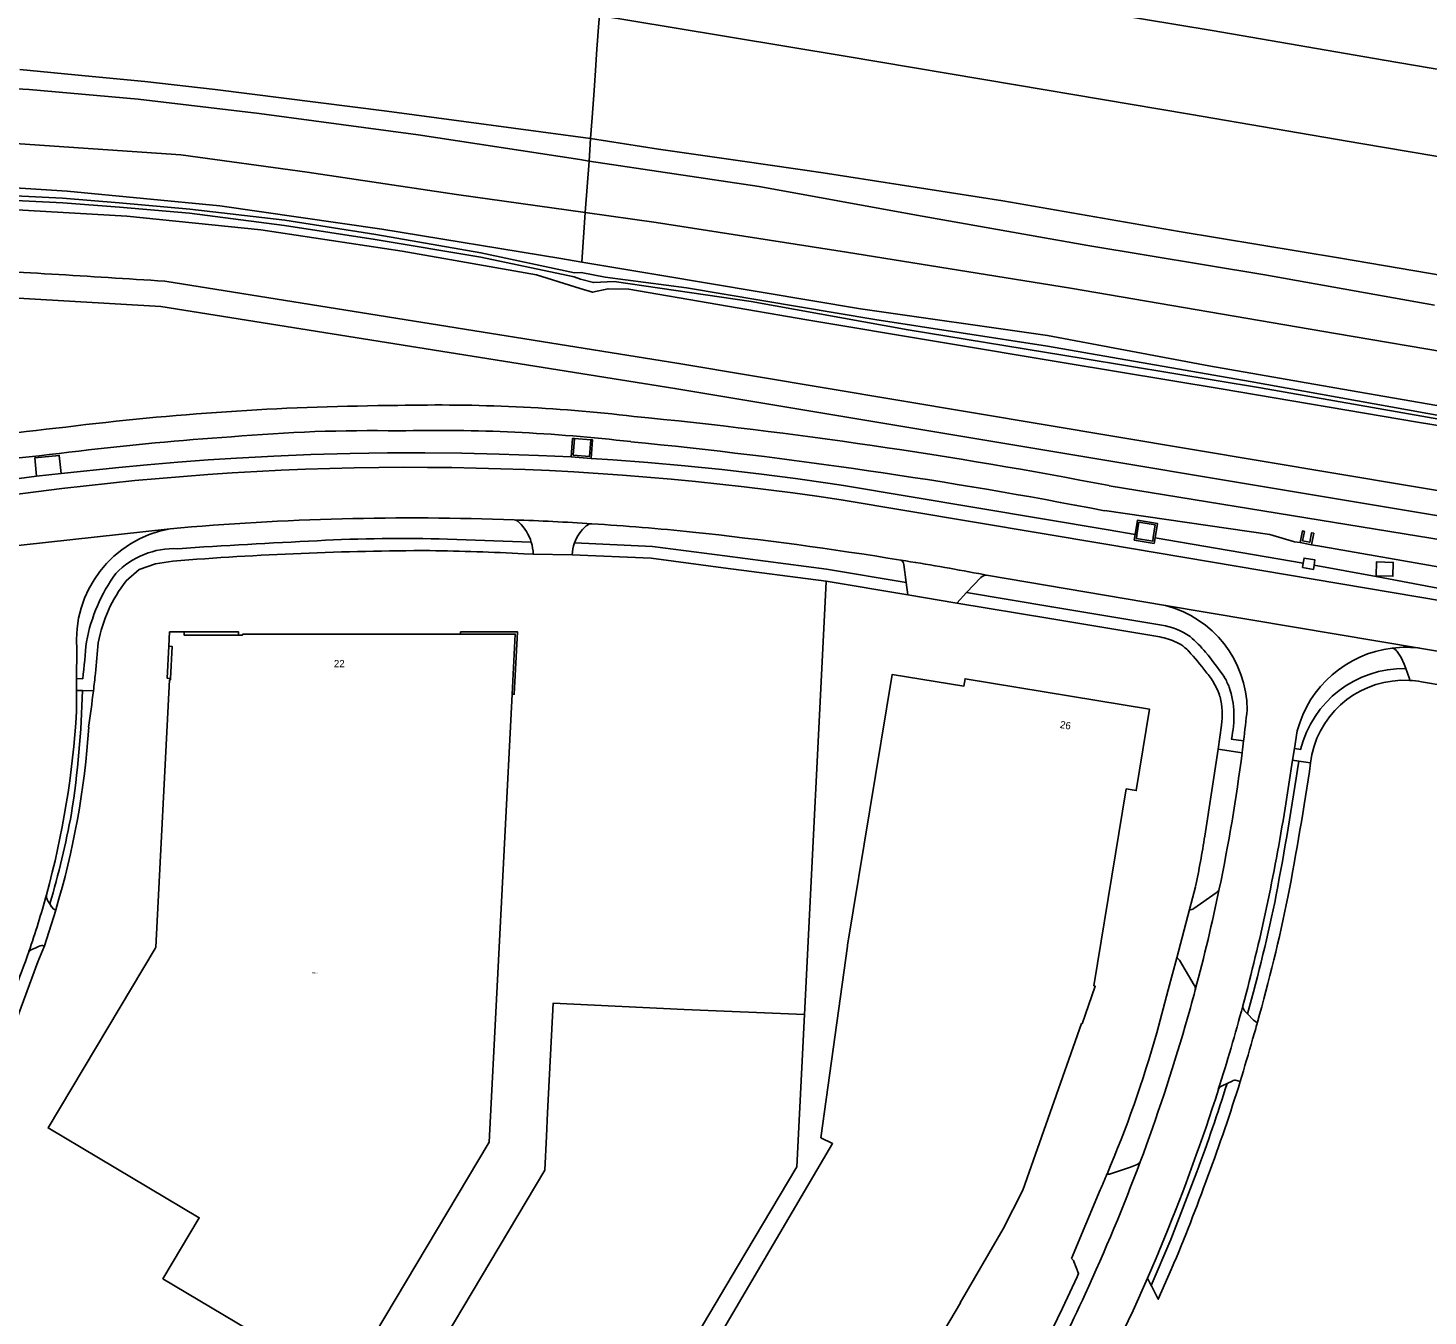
# Model space of a CAD drawing. Extents: x 124000 to 129000, y 395500 to 397503.
# Drawn here: x 125266.3 to 125459, y 395655.6 to 395832.9 of the extents above; entities that cross this region are included whole.
import ezdxf

# ---------------------------------------------------------------- set-up
doc = ezdxf.new("R2010")
doc.units = 0
for name, color, linetype in [('gg-anno-huisnummerreeks BGT', 7, 'Continuous'), ('gg-bbg-luifel en loopbrug', 7, 'Continuous'), ('gg-knt-BGT kruinlijn', 7, 'Continuous'), ('gx-grn-maaiveld', 7, 'Continuous'), ('kenmerkpunt-x pandkandidaat', 7, 'Continuous')]:
    doc.layers.add(name, color=color, linetype=linetype)

msp = doc.modelspace()

# ---------------------------------------------------------------- linework, layer by layer
at = {"layer": 'gg-bbg-luifel en loopbrug'}
for points in [[(125287.82, 395749.78), (125287.82, 395749.35), (125295.32, 395749.35)], [(125287.82, 395749.78), (125295.32, 395749.78), (125295.32, 395749.35)], [(125325.89, 395749.48), (125325.88, 395749.79), (125333.71, 395749.8), (125333.27, 395741.21), (125332.97, 395741.21)], [(125285.95, 395743.39), (125285.51, 395743.41), (125285.74, 395747.81)], [(125285.95, 395743.39), (125286.17, 395747.79), (125285.74, 395747.81)], [(125325.89, 395749.48), (125333.4, 395749.49), (125332.97, 395741.21)]]:
    msp.add_lwpolyline(points, dxfattribs=at)
at = {"layer": 'gg-knt-BGT kruinlijn'}
for p, q in [((125249, 395825.44), (125266.49, 395824.45)), ((125266.49, 395824.45), (125281.51, 395823.15)), ((125281.51, 395823.15), (125298.16, 395821.18)), ((125298.16, 395821.18), (125320.05, 395818.24)), ((125320.05, 395818.24), (125342.31, 395814.81)), ((125342.31, 395814.81), (125343.56, 395814.62)), ((125343.56, 395814.62), (125366.96, 395811.12)), ((125366.96, 395811.12), (125388.64, 395807.15)), ((125388.64, 395807.15), (125412.21, 395803.01)), ((125412.21, 395803.01), (125436.6, 395798.97)), ((125436.6, 395798.97), (125459.92, 395794.76))]:
    msp.add_line(p, q, dxfattribs=at)
at = {"layer": 'gx-grn-maaiveld'}
for p, q in [((125343.56, 395814.62), (125343.78, 395817.71)), ((125343.56, 395814.62), (125343.05, 395807.51)), ((125343.05, 395807.51), (125342.57, 395800.71)), ((125343.81, 395776.23), (125341.54, 395776.41)), ((125341.09, 395773.91), (125343.86, 395773.68)), ((125267.51, 395771.25), (125270.88, 395771.59)), ((125271, 395769.51), (125261.18, 395768.27)), ((125415.17, 395769.92), (125490.09, 395757.69)), ((125249.64, 395759.98), (125285.9, 395764)), ((125335.61, 395762.16), (125324.06, 395762.55)), ((125421.48, 395762.74), (125441.88, 395759.24)), ((125441.44, 395762.09), (125443.02, 395761.78)), ((125334.58, 395760.55), (125335.88, 395760.5)), ((125341.23, 395760.41), (125335.88, 395760.5)), ((125387.22, 395756.57), (125386.9, 395759.09)), ((125398.26, 395757.62), (125397.2, 395757.81)), ((125398.26, 395757.62), (125422.91, 395753.4)), ((125387.44, 395754.87), (125376.2, 395756.78)), ((125387.44, 395754.87), (125387.22, 395756.57)), ((125397.5, 395757.29), (125395.53, 395755.19)), ((125394.18, 395753.75), (125387.44, 395754.87)), ((125394.18, 395753.75), (125395.53, 395755.19)), ((125458.17, 395747.52), (125422.91, 395753.4)), ((125273.05, 395747.27), (125273.03, 395743.36)), ((125466.36, 395746.12), (125458.17, 395747.52)), ((125273.03, 395743.36), (125273.02, 395741.72)), ((125273.03, 395743.36), (125273.88, 395743.34)), ((125458.13, 395742.91), (125461.4, 395742.35)), ((125273.02, 395741.72), (125273.01, 395738.82)), ((125273.82, 395741.71), (125273.02, 395741.72)), ((125275.34, 395741.69), (125273.82, 395741.71)), ((125430.18, 395733.63), (125430.62, 395736.95)), ((125441.03, 395736.16), (125440.65, 395733.73)), ((125433.66, 395734.78), (125431.97, 395735.04)), ((125430.18, 395733.63), (125428.31, 395721.68)), ((125433.46, 395733.16), (125430.18, 395733.63)), ((125440.65, 395733.73), (125440.4, 395732.11)), ((125440.65, 395733.73), (125441.52, 395733.59)), ((125440.4, 395732.11), (125439.37, 395725.51)), ((125441.26, 395731.98), (125440.4, 395732.11)), ((125441.26, 395731.98), (125442.89, 395731.74)), ((125427.04, 395714.71), (125426.2, 395711.55)), ((125429.89, 395713.88), (125426.82, 395711.69)), ((125270.15, 395711.49), (125268.6, 395706.57)), ((125269.34, 395712.34), (125269.06, 395712.77)), ((125269.59, 395711.94), (125269.34, 395712.34)), ((125426.2, 395711.55), (125424.45, 395704.91)), ((125424.83, 395704.57), (125426.88, 395701.16)), ((125409.99, 395663.51), (125413.94, 395672.96)), ((125420.43, 395660.79), (125420.95, 395659.78))]:
    msp.add_line(p, q, dxfattribs=at)
for points in [[(125345.82, 395846.55), (125359.02, 395844.27), (125382.53, 395840.39), (125405.97, 395836.45), (125429.34, 395832.58), (125453, 395828.49), (125476.47, 395824.51), (125500.09, 395820.42), (125523.87, 395816.31), (125547.16, 395812.24), (125570.39, 395808.12), (125593.59, 395803.85), (125601.6, 395802.35)], [(125344.98, 395834.66), (125344.9, 395833.63), (125344.65, 395830), (125344.39, 395826.38), (125344.25, 395824.33), (125343.98, 395820.61), (125343.78, 395817.71)], [(125344.98, 395834.66), (125354.72, 395833.06), (125378.81, 395829.06), (125402.27, 395825.11), (125426.2, 395821.07), (125449.79, 395817.05), (125473.42, 395813.02), (125497.28, 395808.92), (125520.58, 395804.95), (125544.59, 395800.78), (125567.99, 395796.56), (125591.71, 395792.24), (125614.95, 395787.93), (125638.82, 395783.33), (125662.54, 395778.66), (125685.78, 395773.83), (125713.39, 395767.84)], [(125265.21, 395827.21), (125274.22, 395826.33), (125282.42, 395825.55), (125292.12, 395824.46), (125315.71, 395821.5), (125343.78, 395817.71)], [(125343.05, 395807.51), (125325.34, 395809.99), (125304.78, 395813.08), (125287.39, 395815.49), (125265.27, 395816.98), (125249.19, 395817.58), (125228.59, 395817.85), (125207.15, 395818.11), (125183.87, 395817.63), (125158.24, 395817.47), (125133.43, 395817.52), (125099.73, 395817.55), (125068.88, 395817.77), (125053.79, 395818.14), (125033.24, 395818.34), (125017.43, 395818.54), (125006.18, 395819.09), (124994.47, 395819.98), (124980.21, 395821.12), (124962.85, 395822.35)], [(124962.28, 395818.57), (124972.22, 395817.56), (124999.7, 395815.15), (125016.69, 395813.88), (125039.53, 395813.01), (125062.11, 395812.56), (125082.26, 395812.22), (125109.45, 395811.99), (125134.05, 395811.74), (125159.11, 395811.6), (125182.8, 395811.62), (125228, 395812.21), (125250.9, 395811.79), (125271.73, 395810.48), (125292.72, 395808.46), (125315.02, 395805.25), (125339.66, 395801.2), (125342.57, 395800.71)], [(125713.06, 395753.85), (125707.17, 395754.82), (125682.9, 395759.05), (125660.68, 395763.07), (125637.62, 395767.22), (125613, 395771.82), (125588.75, 395776.22), (125566.11, 395780.39), (125542.27, 395784.45), (125518.89, 395788.81), (125495.11, 395792.93), (125471.25, 395797.12), (125447, 395801.24), (125424.8, 395804.9), (125400.53, 395809.12), (125375.8, 395812.98), (125364.69, 395814.58), (125353.12, 395816.27), (125343.78, 395817.71)], [(125345.77, 395798.65), (125342.47, 395799.26), (125341.57, 395799.24), (125328.68, 395802), (125314.21, 395804.49), (125301.68, 395806.48), (125288.6, 395807.97), (125278.88, 395808.86), (125271.1, 395809.51), (125260.79, 395810.03)], [(125260.88, 395809.38), (125271.14, 395808.87), (125278.95, 395808.27), (125288.56, 395807.44), (125301.62, 395805.75), (125314.11, 395803.82), (125328.65, 395801.39), (125341.51, 395798.69), (125342.4, 395798.35), (125344.17, 395797.88), (125347.02, 395798.02), (125365.9, 395795.27), (125387.48, 395791.36), (125411.57, 395787.44), (125435.97, 395783.39), (125462.37, 395778.77), (125490.69, 395774.17), (125518.69, 395769.47), (125541.43, 395766.47), (125564.06, 395762.87), (125584.4, 395759.25)], [(125502.73, 395771.37), (125484.7, 395774.24), (125457.62, 395778.68), (125430.56, 395783.27), (125409.25, 395786.8), (125373.53, 395792.76), (125349.02, 395796.99), (125346.19, 395797.04), (125344.06, 395796.55), (125342.32, 395797.09), (125336.35, 395798.96), (125317.83, 395802.21), (125298.38, 395805.14), (125279.92, 395807.03), (125261.58, 395808.1)], [(125712.87, 395745.87), (125701.58, 395748.17), (125675.43, 395752.9), (125649.11, 395757.15), (125626.09, 395761.17), (125601.29, 395765.34), (125574.24, 395770.23), (125543.08, 395774.92), (125512.53, 395780.27), (125480.9, 395784.98), (125446.33, 395790.87), (125409.82, 395797.11), (125379, 395802.07), (125352.78, 395806.15), (125343.05, 395807.51)], [(125342.57, 395800.71), (125353.3, 395798.89), (125380.93, 395794.29)], [(125493.38, 395763.53), (125486.66, 395764.85), (125355.93, 395786.76), (125285.18, 395798.07)], [(125598.31, 395757.26), (125575.93, 395761.16), (125553.6, 395764.89), (125529.52, 395768.4), (125508.41, 395771.71), (125485.63, 395775.64), (125461.32, 395779.46), (125434.56, 395784.27), (125406.65, 395789.13), (125382.92, 395792.78), (125356.96, 395797.14), (125345.77, 395798.65)], [(125491.34, 395760.61), (125355.38, 395783.3), (125284.63, 395794.61), (125253.93, 395796.4)], [(125428.89, 395786.41), (125406.65, 395790.59), (125380.93, 395794.29)], [(125486.61, 395776.68), (125467.43, 395779.73), (125448.34, 395783.04), (125428.89, 395786.41)], [(125341.54, 395776.41), (125341.29, 395776.43), (125341.09, 395773.91)], [(125343.81, 395776.23), (125343.63, 395773.95), (125341.36, 395774.14), (125341.54, 395776.41)], [(125343.86, 395773.68), (125344.06, 395776.21), (125343.81, 395776.23)], [(125267.51, 395771.25), (125267.26, 395773.74), (125270.64, 395774.08), (125270.88, 395771.59)], [(125270.88, 395771.59), (125278.84, 395772.4), (125282.74, 395772.78), (125286.94, 395773.14), (125291.14, 395773.46), (125295.05, 395773.72), (125300.17, 395774), (125305.28, 395774.21), (125310.7, 395774.36), (125315.82, 395774.43), (125320.94, 395774.44), (125326.07, 395774.38), (125331.19, 395774.26), (125336.6, 395774.06), (125341.09, 395773.91)], [(125418.74, 395763.21), (125415.01, 395763.85), (125378.57, 395769.95), (125376.76, 395770.22), (125372, 395770.89), (125366.92, 395771.54), (125361.83, 395772.13), (125356.74, 395772.65), (125351.64, 395773.1), (125346.83, 395773.47), (125343.86, 395773.68)], [(125267.51, 395771.25), (125255.52, 395769.63), (125248.38, 395768.88), (125241.23, 395768.21), (125233.21, 395767.58), (125225.19, 395767.05), (125217.44, 395766.64), (125209.41, 395766.33), (125201.37, 395766.12), (125193.33, 395766.03), (125185.29, 395766.05), (125177.25, 395766.17), (125169.5, 395766.4), (125161.75, 395766.72), (125158.03, 395766.92), (125143.8, 395767.8)], [(125479.12, 395751.01), (125414.68, 395761.88), (125378.26, 395767.97)], [(125441.44, 395762.09), (125440.67, 395762.2), (125437.28, 395763.19), (125414.5, 395766.48)], [(125421.48, 395762.74), (125421.8, 395764.73), (125419.05, 395765.17), (125418.74, 395763.21)], [(125418.74, 395763.21), (125418.61, 395762.42), (125421.35, 395761.98), (125421.48, 395762.74)], [(125421.23, 395762.78), (125421.15, 395762.27), (125418.9, 395762.63), (125418.98, 395763.17), (125419.26, 395764.88), (125421.51, 395764.52), (125421.23, 395762.78)], [(125443.02, 395761.78), (125443.33, 395763.37), (125443.03, 395763.43), (125442.78, 395762.13), (125441.79, 395762.33), (125442.04, 395763.62), (125441.75, 395763.68), (125441.44, 395762.09)], [(125341.57, 395762.04), (125352.28, 395761.55), (125362.24, 395760.25), (125376.25, 395758.42), (125387.22, 395756.57)], [(125443.02, 395761.78), (125444.43, 395761.53), (125464.63, 395758.03), (125495.66, 395753.35)], [(125279.84, 395756.8), (125281.63, 395758.36), (125283.89, 395759.18), (125286.26, 395759.53)], [(125376.2, 395756.78), (125362.03, 395758.63), (125352.13, 395759.92), (125341.23, 395760.41)], [(125443.37, 395758.98), (125443.48, 395759.69), (125442, 395759.94), (125441.88, 395759.24)], [(125451.9, 395757.52), (125451.94, 395759.42), (125454.26, 395759.36), (125454.22, 395757.46), (125451.9, 395757.52)], [(125441.88, 395759.24), (125441.78, 395758.66), (125443.27, 395758.4), (125443.37, 395758.98)], [(125465.73, 395754.79), (125451.89, 395757.4), (125443.37, 395758.98)], [(125373.21, 395697.09), (125376.19, 395756.68), (125376.2, 395756.78)], [(125422.14, 395749.1), (125406.99, 395751.61), (125394.18, 395753.75)], [(125395.53, 395755.19), (125407.26, 395753.23), (125422.4, 395750.71)], [(125285.74, 395747.81), (125285.83, 395749.78), (125287.82, 395749.78)], [(125295.32, 395749.35), (125295.87, 395749.35), (125295.87, 395749.47), (125325.89, 395749.48)], [(125455.98, 395744.76), (125455.77, 395745.35), (125455.33, 395746.25), (125454.8, 395747.11), (125454.73, 395747.2), (125454.58, 395747.35), (125454.53, 395747.38), (125454.34, 395747.49), (125454.13, 395747.56)], [(125379.12, 395706.51), (125379.14, 395706.65), (125385.28, 395743.91), (125395.14, 395742.3), (125395.32, 395743.34), (125420.73, 395739.13), (125418.89, 395727.95), (125417.5, 395728.18), (125413.07, 395701.06), (125413.24, 395701), (125411.44, 395695.84), (125411.37, 395695.86), (125403.29, 395672.92), (125400.58, 395667.6), (125394.65, 395657.43), (125394.68, 395657.4), (125371.41, 395618.19)], [(125456.48, 395743.11), (125456.5, 395743.16), (125456.51, 395743.24), (125456.51, 395743.32), (125456.51, 395743.32), (125456.49, 395743.4), (125456.46, 395743.47), (125455.98, 395744.76)], [(125332.97, 395741.21), (125329.83, 395679.55), (125309.77, 395645.9), (125309.34, 395646.16), (125303.33, 395649.74), (125284.9, 395660.74), (125289.9, 395669.12), (125269.09, 395681.5), (125283.83, 395706.19), (125283.93, 395706.37), (125285.81, 395743.18), (125285.94, 395743.17), (125285.95, 395743.39)], [(125442.89, 395731.74), (125442.97, 395732.31), (125443.06, 395732.89)], [(125268.6, 395706.57), (125267.67, 395704.37), (125264.59, 395695.88), (125263.34, 395693.3), (125254.54, 395676.71)], [(125266.88, 395706.08), (125267.4, 395706.3), (125267.8, 395706.47)], [(125328.22, 395596.14), (125377.08, 395679.35), (125375.49, 395680.15), (125379.12, 395706.51)], [(125424.45, 395704.91), (125423.28, 395700.49), (125421.7, 395694.58)], [(125291.06, 395597.77), (125313.75, 395635.85), (125337.46, 395675.69), (125337.7, 395680.37), (125337.86, 395683.59), (125338.64, 395698.68), (125356.64, 395697.8), (125373.21, 395697.09)], [(125434.2, 395697.2), (125433.84, 395697.58), (125433.8, 395697.62), (125433.69, 395697.79), (125433.64, 395697.88), (125433.58, 395698.07), (125433.56, 395698.3)], [(125316.87, 395582.92), (125364.01, 395662.4), (125372.17, 395676.15), (125373.21, 395697.09)], [(125434.2, 395697.2), (125435.03, 395696.34), (125435.15, 395696.22), (125435.29, 395696.13), (125435.33, 395696.11), (125435.49, 395696.05), (125435.58, 395696.04)], [(125433.2, 395687.9), (125432.87, 395687.99), (125432.86, 395687.99), (125432.71, 395688.04), (125432.55, 395688.06), (125432.39, 395688.05), (125432.24, 395688.01), (125432.09, 395687.94), (125431.39, 395687.61)], [(125431.39, 395687.61), (125430.7, 395687.29), (125430.55, 395687.2), (125430.39, 395687.07), (125430.3, 395686.96), (125430.18, 395686.77)], [(125415.22, 395675.14), (125418.08, 395676.08), (125419.02, 395676.47)], [(125427.21, 395675.44), (125423.66, 395666.15), (125420.95, 395659.78)], [(125422.79, 395666.37), (125421.63, 395663.57), (125420.43, 395660.79)], [(125316.87, 395582.92), (125342.59, 395568.13), (125345.33, 395566.56), (125358.22, 395582.07), (125388.6, 395621.6), (125391.9, 395626.57), (125395.11, 395631.63), (125397.63, 395635.8), (125400, 395639.89), (125401.97, 395643.43), (125402.3, 395644.03), (125404.53, 395648.21), (125406.67, 395652.42), (125408.74, 395656.68), (125410.74, 395660.97), (125410.95, 395661.46), (125410.29, 395663.12)], [(125420.95, 395659.78), (125421.01, 395659.67), (125421.91, 395657.91), (125423.74, 395662.08)], [(125420.43, 395660.79), (125418.46, 395656.38), (125413.73, 395646.58)]]:
    msp.add_lwpolyline(points, dxfattribs=at)
for centre, radius, start, end in [((125155.33, 393849.91), 1952.48, 86.18672, 87.10278), ((125319.63, 395391.82), 389.15, 90.3502, 96.8924), ((125322.73, 395548.98), 232.05, 83.3214, 91.3523), ((125279.8, 395070.49), 712.41, 79.04661, 84.36831), ((125131.39, 396975.4), 1205.58, 274.64631, 276.74204), ((125319.47, 395393.69), 383.78, 93.7563, 96.9023), ((125313.58, 395560.62), 216.88, 89.0095, 95.0934), ((125322.72, 395548.9), 228.63, 83.3234, 91.3511), ((125279.71, 395069.92), 709.48, 79.04824, 84.37081), ((125131.57, 396973.79), 1207.46, 274.64697, 276.74298), ((125319.04, 395378.42), 394.03, 81.356, 97.002), ((125319.28, 395388.98), 376.5, 87.8729, 95.0861), ((125333.14, 395764.24), 0.991, 37.7964, 83.7783), ((125319.04, 395379.54), 385.94, 86.3014, 87.8893), ((125288.66, 395748.58), 15.66, 100.1621, 184.8117), ((125329.77, 395760.36), 6.11, 17.0288, 47.116), ((125346.97, 395760.07), 5.75, 131.4553, 159.9405), ((125343.95, 395763.52), 1.16, 90.6578, 132.4038), ((125319.2, 395381.53), 383.95, 84.2268, 86.3067), ((125303.24, 395249.59), 516.83, 80.7305, 83.9381), ((125286.47, 395750.03), 11.22, 87.5702, 135.9354), ((125345.89, 394897.69), 865.56, 92.63179, 93.90443), ((125317.46, 395551.34), 211.31, 88.2101, 93.0692), ((125329.79, 395760.37), 6.09, 1.2558, 17.0384), ((125346.97, 395760.07), 5.75, 160.0265, 176.6367), ((125323.04, 395296.24), 464.75, 90.171, 94.5398), ((125317.2, 395437.96), 323.05, 86.9167, 89.2107), ((125304.15, 395254.95), 511.4, 79.5172, 80.7344), ((125386.14, 395758.99), 0.762, 6.9657, 62.689), ((125297.9, 395743.91), 23.96, 144.4373, 169.1008), ((125398.29, 395756.52), 1.1, 91.3103, 136.0033), ((125295.52, 395744.62), 19.86, 142.1586, 169.3086), ((125419.21, 395738.93), 14.94, 0.5107, 75.6426), ((125420.95, 395741.51), 9.32, 54.998, 81.0445), ((125078.21, 395764.78), 196.84, 353.7477, 355.2368), ((125089.24, 395763.74), 187.4, 353.9754, 355.2744), ((125420.67, 395740.64), 8.58, 63.8522, 80.1987), ((125422.24, 395743.66), 5.18, 50.444, 64.6547), ((125416.92, 395737.85), 14.68, 38.4863, 50.3075), ((125422.2, 395743.63), 5.23, 41.7116, 50.3454), ((125400.46, 395723.18), 35.08, 37.0422, 43.0183), ((125397.12, 395720.61), 40.93, 34.0997, 40.115), ((125456, 395732.19), 15.48, 96.9191, 165.1523), ((125456, 395732.14), 15.53, 81.9571, 96.9087), ((125079.18, 395764.7), 197.51, 353.3092, 354.0051), ((125421.33, 395738), 9.52, 29.899, 41.5083), ((125455.78, 395730.07), 14.69, 89.2163, 166.13), ((125421.36, 395738.02), 9.48, 17.282, 29.8885), ((125422.39, 395738.53), 9.98, 21.3236, 30.2563), ((125419.35, 395738.09), 12.99, 346.3912, 18.2408), ((125455.77, 395730.11), 13.02, 86.8785, 167.6668), ((125455.81, 395730.42), 12.71, 79.4783, 86.9812), ((125146.25, 395744.55), 127.6, 351.1021, 358.7243), ((125083.57, 395764.21), 193.09, 351.7978, 353.3013), ((125420.82, 395738.39), 9.91, 351.6741, 14.3112), ((125150.44, 395745.92), 122.77, 344.7405, 356.6837), ((125168.35, 395766.82), 267.24, 353.1143, 354.0379), ((125162.59, 395743.89), 112.33, 343.2404, 356.313), ((125220.07, 395760.71), 215.16, 352.6444, 353.0795), ((125187.11, 395764.77), 248.37, 348.2991, 352.6871), ((124989.27, 395798.69), 456.88, 349.2636, 351.6038), ((124969.14, 395802.28), 478.97, 349.2909, 351.5309), ((125158.14, 395745.52), 116.04, 343.3834, 349.7169), ((125174.84, 395767.75), 267.88, 344.9734, 350.928), ((125324.12, 395737.08), 105.32, 347.7377, 351.5889), ((125149.82, 395746.09), 123.41, 340.9269, 344.7405), ((125270.07, 395713.42), 1.2, 171.0954, 212.7854), ((125187.66, 395764.69), 247.81, 344.9876, 348.2931), ((125429.19, 395714.89), 1.23, 304.6956, 336.6662), ((125203.33, 395761.66), 239.7, 344.4013, 348.4301), ((125203.36, 395761.63), 241.3, 344.2278, 348.4408), ((125270.32, 395712.27), 0.794, 204.421, 257.5791), ((125426.31, 395712.45), 0.91, 262.8692, 303.4872), ((125149.68, 395746.2), 123.58, 335.5796, 340.8974), ((125267.31, 395705.07), 1.1, 113.5109, 141.1053), ((125268.34, 395705.39), 1.21, 77.4045, 116.6005), ((125424.23, 395704.28), 0.663, 25.9905, 71.1721), ((125179.19, 395767.03), 256.6, 343.8261, 344.9728), ((125425.92, 395700.62), 1.11, 353.7181, 29.4323), ((125176.9, 395767.19), 265.74, 342.3846, 344.9752), ((125173.45, 395770.3), 272.44, 343.6735, 344.1817), ((125258, 395741.15), 170.2, 337.1686, 344.1168), ((125173.16, 395768.69), 262.85, 339.5458, 343.8435), ((125203.54, 395758.63), 240.3, 342.8811, 344.3281), ((125174.78, 395767.82), 267.96, 337.7523, 342.3929), ((125212.81, 395755.87), 228.99, 339.4354, 342.6557), ((125211.06, 395756.48), 232.48, 339.448, 342.8428), ((125174.02, 395768.32), 261.91, 335.235, 339.557), ((125418.65, 395677.33), 0.932, 293.5437, 328.1078), ((125286.48, 395728.9), 139.19, 336.3034, 337.2673), ((125414.95, 395676.21), 1.1, 265.377, 284.2033), ((125211.18, 395752.75), 231.09, 336.8987, 340.303), ((125409.43, 395662.76), 0.93, 22.9116, 53.2309), ((125173.63, 395768.41), 262.31, 328.9142, 335.2516)]:
    msp.add_arc(centre, radius, start, end, dxfattribs=at)

# ---------------------------------------------------------------- texts
at = {"layer": 'gg-anno-huisnummerreeks BGT'}
msp.add_text('22', height=1, dxfattribs=at).set_placement((125308.44, 395744.92))
msp.add_text('26', height=1, rotation=350.6, dxfattribs=at).set_placement((125408.33, 395736.57))
at = {"layer": 'kenmerkpunt-x pandkandidaat'}
msp.add_text('PNDK', height=0.2, dxfattribs=at).set_placement((125305.46, 395702.74))

doc.saveas('drawing.dxf')
